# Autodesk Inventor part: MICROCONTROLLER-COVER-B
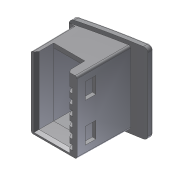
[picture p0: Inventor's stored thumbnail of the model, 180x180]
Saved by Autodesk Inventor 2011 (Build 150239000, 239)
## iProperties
Created: 2010-06
Part Number: MICROCONTROLLER-COVER-B
Document SubType Name: Modeling
Designer: kurdi
Density: 1 g/cm^3
Author: kurdi
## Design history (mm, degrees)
feature "Base1"
node "NONE"
